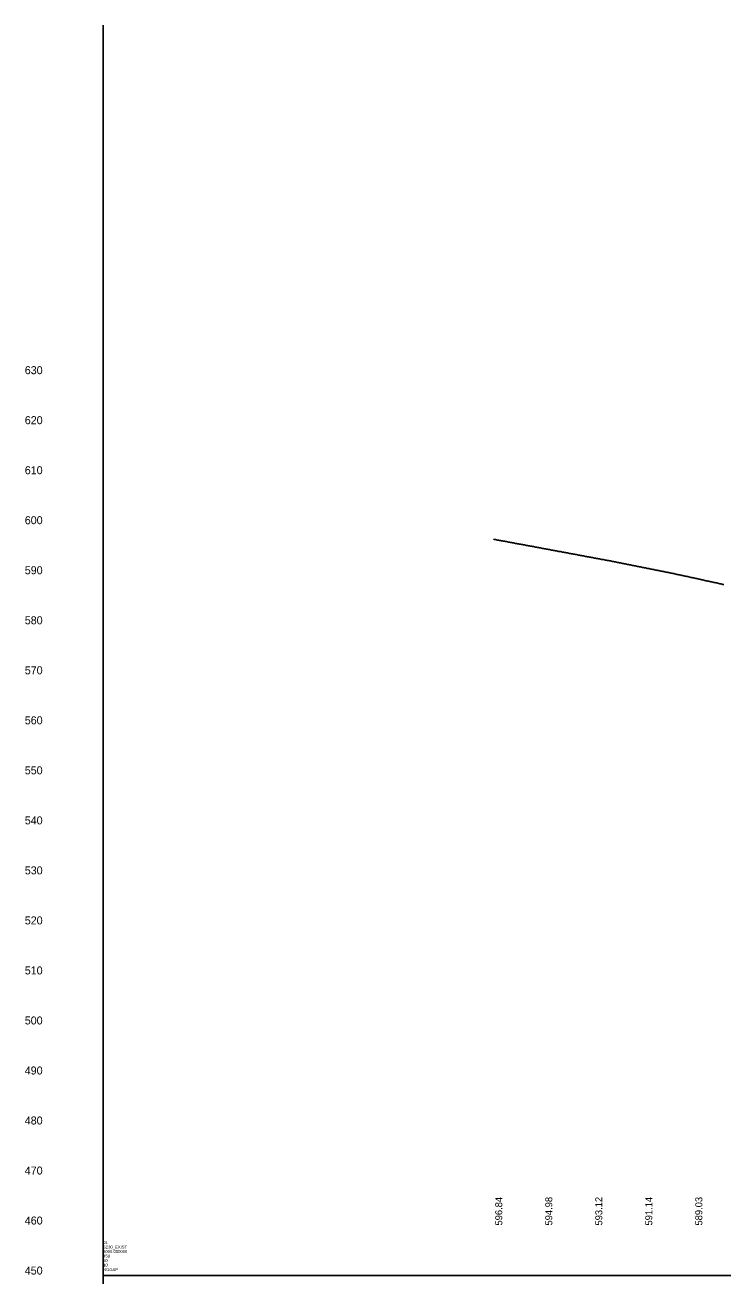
# Model space of a CAD drawing. Extents: x 1622419 to 1631737, y 887848 to 892020.
# Drawn here: x 1622419 to 1623117, y 890770 to 892020 of the extents above; entities that cross this region are included whole.
import ezdxf

# ---------------------------------------------------------------- set-up
doc = ezdxf.new("R2010")
doc.units = 0
for name, color, linetype in [('RD_DDB_ElevTX', 7, 'Continuous'), ('RD_DDB_Profile_EX', 7, 'Continuous'), ('RD_DDB_StripGrade', 7, 'Continuous'), ('RD_GPK_Profile_Cell', 7, 'Continuous')]:
    doc.layers.add(name, color=color, linetype=linetype)

msp = doc.modelspace()

# ---------------------------------------------------------------- linework, layer by layer
at = {"layer": 'RD_DDB_Profile_EX'}
for points in [[(1622887.4, 891506), (1622888.4, 891505.8), (1622889.4, 891505.6), (1622890.4, 891505.4), (1622891.4, 891505.2), (1622892.4, 891505.1), (1622893.4, 891504.9), (1622894.4, 891504.7), (1622895.4, 891504.5), (1622896.4, 891504.3), (1622897.4, 891504.1), (1622898.4, 891504), (1622899.4, 891503.8), (1622900.4, 891503.6), (1622901.4, 891503.4), (1622902.4, 891503.2), (1622903.4, 891503), (1622904.4, 891502.8), (1622905.4, 891502.7), (1622906.4, 891502.5), (1622907.4, 891502.3), (1622908.4, 891502.1), (1622909.4, 891501.9), (1622910.4, 891501.7), (1622911.4, 891501.5), (1622912.4, 891501.4), (1622913.4, 891501.2), (1622914.4, 891501), (1622915.4, 891500.8), (1622916.4, 891500.6), (1622917.4, 891500.4), (1622918.4, 891500.3), (1622919.4, 891500.1), (1622920.4, 891499.9), (1622921.4, 891499.7), (1622922.4, 891499.5), (1622923.4, 891499.3), (1622924.4, 891499.1), (1622925.4, 891499), (1622926.4, 891498.8), (1622927.4, 891498.6), (1622928.4, 891498.4), (1622929.4, 891498.2), (1622930.4, 891498), (1622931.4, 891497.8), (1622932.4, 891497.7), (1622933.4, 891497.5), (1622934.4, 891497.3), (1622935.4, 891497.1), (1622936.4, 891496.9), (1622937.4, 891496.7), (1622938.4, 891496.5), (1622939.4, 891496.4), (1622940.4, 891496.2), (1622941.4, 891496), (1622942.4, 891495.8), (1622943.4, 891495.6), (1622944.4, 891495.4), (1622945.4, 891495.2), (1622946.4, 891495.1), (1622947.4, 891494.9), (1622948.4, 891494.7), (1622949.4, 891494.5), (1622950.4, 891494.3), (1622951.4, 891494.1), (1622952.4, 891493.9), (1622953.4, 891493.7), (1622954.4, 891493.6), (1622955.4, 891493.4), (1622956.4, 891493.2), (1622957.4, 891493), (1622958.4, 891492.8), (1622959.4, 891492.6), (1622960.4, 891492.4), (1622961.4, 891492.3), (1622962.4, 891492.1), (1622963.4, 891491.9), (1622964.4, 891491.7), (1622965.4, 891491.5), (1622966.4, 891491.3), (1622967.4, 891491.1), (1622968.4, 891491), (1622969.4, 891490.8), (1622970.4, 891490.6), (1622971.4, 891490.4), (1622972.4, 891490.2), (1622973.4, 891490), (1622974.4, 891489.8), (1622975.4, 891489.7), (1622976.4, 891489.5), (1622977.4, 891489.3), (1622978.4, 891489.1), (1622979.4, 891488.9), (1622980.4, 891488.7), (1622981.4, 891488.5), (1622982.4, 891488.4), (1622983.4, 891488.2), (1622984.4, 891488), (1622985.4, 891487.8), (1622986.4, 891487.6), (1622987.4, 891487.4)], [(1622987.4, 891487.4), (1622988.4, 891487.2), (1622989.4, 891487.1), (1622990.4, 891486.9), (1622991.4, 891486.7), (1622992.4, 891486.5), (1622993.4, 891486.3), (1622994.4, 891486.1), (1622995.4, 891485.9), (1622996.4, 891485.7), (1622997.4, 891485.6), (1622998.4, 891485.4), (1622999.4, 891485.2), (1623000.4, 891485), (1623001.4, 891484.8), (1623002.4, 891484.6), (1623003.4, 891484.4), (1623004.4, 891484.3), (1623005.4, 891484.1), (1623006.4, 891483.9), (1623007.4, 891483.7), (1623008.4, 891483.5), (1623009.4, 891483.3), (1623010.4, 891483.1), (1623011.4, 891482.9), (1623012.4, 891482.7), (1623013.4, 891482.5), (1623014.4, 891482.3), (1623015.4, 891482.1), (1623016.4, 891481.9), (1623017.4, 891481.7), (1623018.4, 891481.5), (1623019.4, 891481.3), (1623020.4, 891481.1), (1623021.4, 891480.9), (1623022.4, 891480.7), (1623023.4, 891480.5), (1623024.4, 891480.3), (1623025.4, 891480.1), (1623026.4, 891479.9), (1623027.4, 891479.7), (1623028.4, 891479.5), (1623029.4, 891479.3), (1623030.4, 891479.1), (1623031.4, 891478.9), (1623032.4, 891478.7), (1623033.4, 891478.5), (1623034.4, 891478.3), (1623035.4, 891478.1), (1623036.4, 891477.9), (1623037.4, 891477.7), (1623038.4, 891477.5), (1623039.4, 891477.3), (1623040.4, 891477.1), (1623041.4, 891476.8), (1623042.4, 891476.6), (1623043.4, 891476.4), (1623044.4, 891476.2), (1623045.4, 891476), (1623046.4, 891475.8), (1623047.4, 891475.6), (1623048.4, 891475.4), (1623049.4, 891475.2), (1623050.4, 891475), (1623051.4, 891474.8), (1623052.4, 891474.6), (1623053.4, 891474.4), (1623054.4, 891474.2), (1623055.4, 891474), (1623056.4, 891473.8), (1623057.4, 891473.6), (1623058.4, 891473.4), (1623059.4, 891473.2), (1623060.4, 891473), (1623061.4, 891472.8), (1623062.4, 891472.6), (1623063.4, 891472.4), (1623064.4, 891472.2), (1623065.4, 891472), (1623066.4, 891471.8), (1623067.4, 891471.6), (1623068.4, 891471.4), (1623069.4, 891471.2), (1623070.4, 891470.9), (1623071.4, 891470.7), (1623072.4, 891470.5), (1623073.4, 891470.3), (1623074.4, 891470.1), (1623075.4, 891469.9), (1623076.4, 891469.6), (1623077.4, 891469.4), (1623078.4, 891469.2), (1623079.4, 891469), (1623080.4, 891468.8), (1623081.4, 891468.6), (1623082.4, 891468.3), (1623083.4, 891468.1), (1623084.4, 891467.9), (1623085.4, 891467.7), (1623086.4, 891467.5), (1623087.4, 891467.3)], [(1623087.4, 891467.3), (1623088.4, 891467), (1623089.4, 891466.8), (1623090.4, 891466.6), (1623091.4, 891466.4), (1623092.4, 891466.2), (1623093.4, 891466), (1623094.4, 891465.7), (1623095.4, 891465.5), (1623096.4, 891465.3), (1623097.4, 891465.1), (1623098.4, 891464.9), (1623099.4, 891464.6), (1623100.4, 891464.4), (1623101.4, 891464.2), (1623102.4, 891464), (1623103.4, 891463.8), (1623104.4, 891463.6), (1623105.4, 891463.3), (1623106.4, 891463.1), (1623107.4, 891462.9), (1623108.4, 891462.7), (1623109.4, 891462.5), (1623110.4, 891462.3), (1623111.4, 891462), (1623112.4, 891461.8), (1623113.4, 891461.6), (1623114.4, 891461.4), (1623115.4, 891461.2), (1623116.4, 891460.9), (1623117.4, 891460.7)]]:
    msp.add_lwpolyline(points, dxfattribs=at)
at = {"layer": 'RD_GPK_Profile_Cell'}
for q in [(1622497, 892020), (1623797, 890770), (1622497, 889520)]:
    msp.add_line((1622497, 890770), q, dxfattribs=at)

# ---------------------------------------------------------------- texts
at = {"layer": 'RD_DDB_ElevTX'}
for s, p in [('630', (1622418.7, 891671)), ('620', (1622418.7, 891621)), ('610', (1622418.7, 891571)), ('600', (1622418.7, 891521)), ('590', (1622418.7, 891471)), ('580', (1622418.7, 891421)), ('570', (1622418.7, 891371)), ('560', (1622418.7, 891321)), ('550', (1622418.7, 891271)), ('540', (1622418.7, 891221)), ('530', (1622418.7, 891171)), ('520', (1622418.7, 891121)), ('510', (1622418.7, 891071)), ('500', (1622418.7, 891021)), ('490', (1622418.7, 890971)), ('480', (1622418.7, 890921)), ('470', (1622418.7, 890871)), ('460', (1622418.7, 890821)), ('450', (1622418.7, 890771))]:
    msp.add_text(s, height=8, dxfattribs=at).set_placement(p)
at = {"layer": 'RD_DDB_StripGrade'}
for s, p in [('596.84', (1622896, 890820)), ('594.98', (1622946, 890820)), ('593.12', (1622996, 890820)), ('591.14', (1623046, 890820)), ('589.03', (1623096, 890820))]:
    msp.add_text(s, height=7, rotation=90, dxfattribs=at).set_placement(p)
at = {"layer": 'RD_GPK_Profile_Cell'}
for s, p in [('01', (1622497, 890801.5)), ('450', (1622497, 890788)), ('S230_EXIST', (1622497, 890797)), ('6000.000000', (1622497, 890792.5)), ('50', (1622497, 890783.5)), ('10', (1622497, 890779)), ('NOGAP', (1622497, 890774.5))]:
    msp.add_text(s, height=3, dxfattribs=at).set_placement(p)

doc.saveas('drawing.dxf')
